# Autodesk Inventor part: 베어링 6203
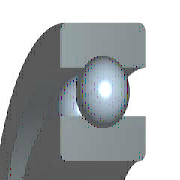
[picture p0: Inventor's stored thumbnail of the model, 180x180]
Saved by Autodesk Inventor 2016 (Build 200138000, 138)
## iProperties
IsCustomPart: 0
Created: 2016-04
Part Number: 베어링 6203
Material: 알루미늄 6061
Description: 깊은 그루브 볼 베어링
Document SubType Name: Modeling
Standard: KS B 2023
Designer: mdu
Standards Organization: KS
Language: ko-KR
Size Designation: 6203 - 17 x 40 x 12
Categories: <MemberInstance><Categories><Category DisplayName="샤프트 부품" InternalName="7f7aeb1f-a693-4053-b835-cee3144e0d98" Mnemonic="SHFT"><Category DisplayName="베어링" Inter
Density: 2.71 g/cm^3
Mass: 22.4044 g
Surface Area: 64.3582 cm^2
Volume: 8.26729 cm^3
Appearance: 알루미늄 - 평지
Author: mdu
Revision Number: 1
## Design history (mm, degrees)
sketch "스케치" dims "d0" = 5.98 (= -0.26 x WD + 0.26 x BD)
  geometry: L1 (3.01, 14.25)-(8.99, 14.25); L2 (6, 14.25)-(6, 11.26); L3 (6, 14.25)-(6, 17.24); L4 (3.778, 12.249)-(0, 12.249); L5 (0, 8.5)-(12, 8.5); L6 (3.778, 16.251)-(0, 16.251); L7 (0, 20)-(12, 20); L8 (12, 8.5)-(12, 12.249); L9 (8.222, 12.249)-(12, 12.249); L10 (8.222, 16.251)-(12, 16.251); L11 (12, 20)-(12, 16.251); L12 (-1.4, 0)-(8.4, 0) reference; L13 (0, -0.3)-(0, 5.3) reference
  constraints: 22 end point, 4 point on line, 2 collinear, 2 perpendicular, 2 symmetric about line, 1 midpoint, 1 parallel, 14 other
  dimensions: "d9" = 17 diameter of L5 L12 (= WD); "d11" = 40 diameter of L7 L12 (= BD); "d12" = 12 distance between parallel lines of L8 L13 (= KB); "d13" = 24.498 diameter of L9 L12 (= 0.326 x BD + 0.674 x WD)
revolve "본체" stored, may be unused: angle "d6" = 90 deg
revolve "볼" stored, may be unused: angle "d7" = 90 deg
pattern_circular "IDS_ARRAYBALL[SIMPL:T]" dims angle "d3" = 360 deg
body "Solid1"
fillet "모깎기1" dims "d1" = 0.6 (= KRS)
other parameters: "WD" = 17 [user parameter; used in 5 equation terms], "BD" = 40 [user parameter; used in 5 equation terms], "KB" = 12 [user parameter; used in 1 equation term], "KRS" = 0.6 [user parameter; used in 1 equation term], "d4" = 0, "d5" = 0, "d8" = 0, "d14" = 0, "d15" = 0, "BBA" = 0 [user parameter], "BC0" = 4750000 [user parameter], "BC" = 9560000 [user parameter], "WR" = 8.5 (= 0.5 x WD) [user parameter]
